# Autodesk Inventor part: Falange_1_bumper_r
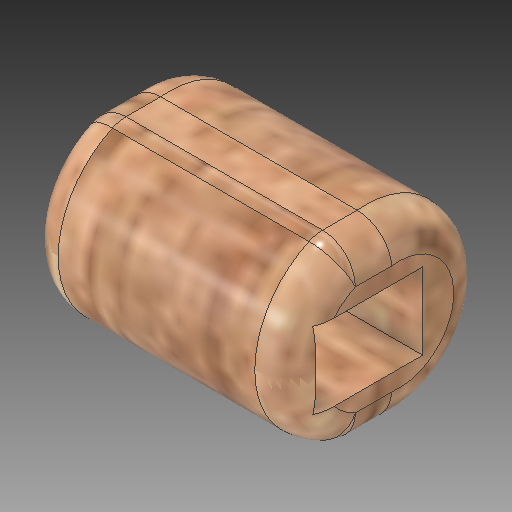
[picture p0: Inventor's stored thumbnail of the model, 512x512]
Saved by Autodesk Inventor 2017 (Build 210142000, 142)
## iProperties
Created: 2017-05
Part Number: Falange_1_bumper_r
Material: Generic
Document SubType Name: Modeling
Designer: alez_
Density: 1 g/cm^3
Appearance: Default
Author: alez_
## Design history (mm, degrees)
derived "Falange_1_bumper.ipt" dims "d0" = 11
feature "Solid1::Falange_1_bumper.ipt" dims "d0" = 11
tag "TaggingFeature1"
body "Solid1"
